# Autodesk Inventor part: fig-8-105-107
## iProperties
Shininess: 64.0
Length Units: 11269
Angle Units: 11279
Time Units: 11290
Mass Units: 11283
Length Display Precision: 3
Angle Display Precision: 2
Compacted: True
Part Number: fig-8-105-107
Document SubType Name: Modeling
Created: 2002-12
Designer: deepak
Density: 1 g/cm^3
Density: 0.0
Volumn: 0.0
Area: 0.0
PropertySet Name: Model Information
Control State: 0
Master: False
Checked Out: False
Author: deepak
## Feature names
1. Extrusion1
2. Shell2
3. Extrusion2
4. Rectangular Pattern1
5. Split2
